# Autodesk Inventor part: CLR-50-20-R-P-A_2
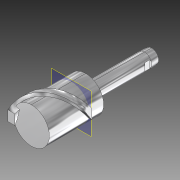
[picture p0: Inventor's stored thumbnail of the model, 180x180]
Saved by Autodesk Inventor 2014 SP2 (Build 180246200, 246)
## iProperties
Shininess: 64.0
Length Units: 11269
Angle Units: 11279
Time Units: 11290
Mass Units: 11283
Length Display Precision: 3
Angle Display Precision: 2
Compacted: True
Part Number: CLR-50-20-R-P-A_2
Document SubType Name: Modeling
Created: 2004-03
Material: Allgemein
Cost Center: 0,2 kg
Designer: Peter Kastler
Manufacturer: Standard
Standards Organization: Custom
Mass: 177.476 g
Surface Area: 244.178 cm^2
Volume: 177.476 cm^3
Density: 1 g/cm^3
Appearance: Chrom
Density: 0.0
Volumn: 0.0
Area: 0.0
PropertySet Name: Model Information
Control State: 0
Master: False
Checked Out: False
Übersetzungsnorm: STEP AP203
Dateiname: 535459_CLR_50_20_R_P_A.stp
Postprozessor: Build: 081d, Release: 8 SP1 - Date: Tue 01/26/2004
Gesendete Einheiten: MILLIMETERS
Unbestimmtheit: 1e-06
TotalMass: 0,2 kg
Cideon_Mass: 0.18
Cideon_Mass_Unit: kg
Cideon_Area: 0,024 m^2
Cideon_User: konstruktion
Cideon_SaveDate: 10.10.2018
Cideon_SaveTime: 09:12:01
Author: Peter Kastler
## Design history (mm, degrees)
feature "Basis1"
workplane "Arbeitsebene2"
sketch "Skizze2"
  geometry: L1 (28.456, 6.538)-(20.11, 6.538); L2 (20.11, 6.538)-(20.11, -6.462); L3 (20.11, -6.462)-(28.456, -6.462); L4 (28.456, -6.462)-(28.456, 6.538); L5 (28.456, 6.538)-(21.947, 6.538); L6 (21.947, 6.538)-(21.947, 9.538); L7 (21.947, 9.538)-(28.456, 9.538); L8 (28.456, 9.538)-(28.456, 6.538); L9 (28.456, -6.462)-(21.947, -6.462); L10 (21.947, -6.462)-(21.947, -9.462); L11 (21.947, -9.462)-(28.456, -9.462); L12 (28.456, -9.462)-(28.456, -6.462)
  constraints: 24 end point, 6 parallel, 3 horizontal, 3 perpendicular
  dimensions: "d12" = 13 distance of L3.end L1.start; "d13" = 3 distance between parallel lines of L7 L1; "d14" = 3 distance between parallel lines of L3 L11 (= d13)
feature "Spirale2" sketch "Skizze2" pitch "d15" = 70; turns "d17" = 0.5; dims "d16" = 10, "d18" = 0, angle "d19" = 90 deg, angle "d20" = 90 deg, "d21" = 0, "d22" = 0
sketch "Skizze3"
  geometry: L1 (0, 0)-(5.315, 0) reference; L2 (5.315, 0)-(5.315, 3) reference; L3 (5.315, 3)-(1.01, 3) reference; L4 (0.99, 16)-(5.315, 16) reference; L5 (5.315, 16)-(5.315, 19) reference; L6 (5.315, 19)-(-0.031, 19) reference; A1 r 25 centre (-23.14, 9.462) between (0, 0) and (1.01, 3) reference; A2 r 25 centre (-23.14, 9.462) between (0.99, 16) and (-0.031, 19) reference
extrude "Extrusion2" join sketch "Skizze3" stored distance "d23" = 10; taper "d24" = 0 deg
node "Volumenkörper1"
node "Volumenkörper"
node "Flächenkörper"
node "Projizierte Kontur1"
other parameters: "d11" = -25
